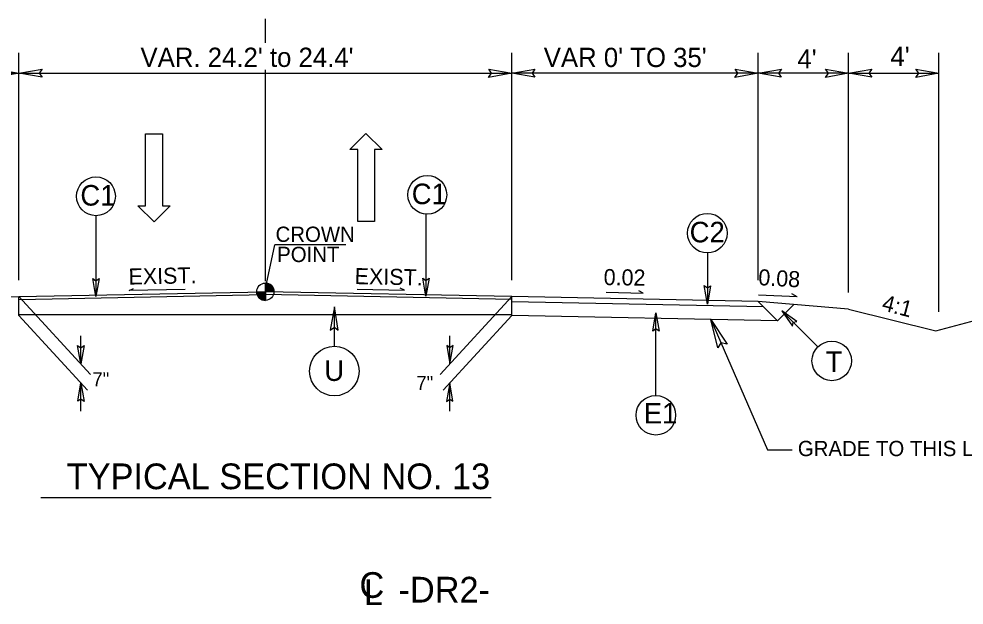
# Model space of a CAD drawing. Extents: x 573813 to 575363, y -54752 to -53123.
# Drawn here: x 574833.5 to 574917.3, y -54169.1 to -54117.2 of the extents above; entities that cross this region are included whole.
import ezdxf

# ---------------------------------------------------------------- set-up
doc = ezdxf.new("R2010")
doc.units = 0
for name, color, linetype in [('Exist CMT Alignment Centerline', 7, 'Continuous'), ('Exist CMT Ground Line', 7, 'Continuous'), ('Old_Level_1', 7, 'Continuous'), ('Old_Level_11', 7, 'Continuous'), ('Old_Level_2', 7, 'Continuous'), ('Old_Level_3', 7, 'Continuous'), ('Pattern 4', 7, 'Continuous'), ('Prop Dimension', 7, 'Continuous'), ('Prop Dimension Text', 7, 'Continuous'), ('Prop Lane Arrow CELL', 7, 'Continuous'), ('Prop Pavement Schedule Description CELL', 7, 'Continuous'), ('Typical Grade Point Symbol CELL', 7, 'Continuous'), ('Typical ID Circle CELL', 7, 'Continuous'), ('Typical Pavement Slope CELL', 7, 'Continuous'), ('Typical Pavement Slope Information CELL', 7, 'Continuous'), ('Typical Shoulder Slope Information CELL', 7, 'Continuous'), ('Typical Terminator CELL', 7, 'Continuous'), ('Typical Text General CELL', 7, 'Continuous'), ('Typical Text ID Circle CELL', 7, 'Continuous'), ('Typical Text Label CELL', 7, 'Continuous')]:
    doc.layers.add(name, color=color, linetype=linetype)

msp = doc.modelspace()

# ---------------------------------------------------------------- linework, layer by layer
at = {"layer": 'Exist CMT Alignment Centerline'}
for p, q in [((574833.535, -54143.346), (574833.535, -54141.771)), ((574833.535, -54143.346), (574833.535, -54141.771)), ((574833.535, -54143.439), (574833.535, -54142.246)), ((574877.195, -54143.346), (574877.195, -54141.771)), ((574877.195, -54143.439), (574877.195, -54142.246))]:
    msp.add_line(p, q, dxfattribs=at)
at = {"layer": 'Exist CMT Ground Line'}
for p, q in [((574833.54, -54142.021), (574855.37, -54141.584)), ((574877.19, -54142.021), (574855.36, -54141.584)), ((574833.535, -54143.346), (574877.195, -54143.346))]:
    msp.add_line(p, q, dxfattribs=at)
at = {"layer": 'Old_Level_1'}
for p, q in [((574914.76, -54144.8), (574933.236, -54139.865)), ((574833.535, -54141.771), (574855.365, -54141.334)), ((574843.311, -54141.23), (574843.691, -54141.041)), ((574848.249, -54141.128), (574843.311, -54141.23)), ((574863.489, -54141.116), (574867.686, -54141.204)), ((574867.686, -54141.204), (574867.307, -54141.014)), ((574885.567, -54141.387), (574888.836, -54141.455)), ((574888.836, -54141.455), (574888.457, -54141.265)), ((574902.47, -54141.8), (574902.016, -54141.508)), ((574811.705, -54142.207), (574833.535, -54141.771)), ((574899.024, -54142.207), (574877.195, -54141.771)), ((574899.489, -54142.671), (574877.204, -54142.226)), ((574907.039, -54142.87), (574899.024, -54142.207)), ((574899.024, -54142.207), (574900.727, -54143.91)), ((574902.47, -54141.8), (574899.041, -54141.634)), ((574902.169, -54142.467), (574900.727, -54143.91)), ((574907.039, -54142.87), (574914.76, -54144.8)), ((574900.727, -54143.91), (574877.204, -54143.439))]:
    msp.add_line(p, q, dxfattribs=at)
at = {"layer": 'Old_Level_11'}
for p, q in [((574915.043, -54143.1), (574915.043, -54120.185)), ((574907.039, -54122.004), (574915.043, -54122.004)), ((574855.365, -54141.05), (574856.217, -54137.177)), ((574862.482, -54137.177), (574856.217, -54137.177))]:
    msp.add_line(p, q, dxfattribs=at)
for points in [[(574831.488, -54121.651), (574833.535, -54122.004), (574831.477, -54122.367), (574831.738, -54122.004)], [(574835.581, -54122.356), (574833.535, -54122.004), (574835.593, -54121.64), (574835.331, -54122.004)], [(574875.148, -54121.651), (574877.195, -54122.004), (574875.137, -54122.367), (574875.398, -54122.004)], [(574879.241, -54122.356), (574877.195, -54122.004), (574879.252, -54121.64), (574878.991, -54122.004)], [(574896.978, -54121.651), (574899.024, -54122.004), (574896.967, -54122.367), (574897.228, -54122.004)], [(574901.071, -54122.356), (574899.024, -54122.004), (574901.082, -54121.64), (574900.821, -54122.004)], [(574904.993, -54121.651), (574907.039, -54122.004), (574904.982, -54122.367), (574905.243, -54122.004)], [(574909.086, -54122.356), (574907.039, -54122.004), (574909.097, -54121.64), (574908.836, -54122.004)], [(574912.997, -54121.652), (574915.043, -54122.004), (574912.986, -54122.368), (574913.247, -54122.004)]]:
    msp.add_lwpolyline(points, close=True, dxfattribs=at)
at = {"layer": 'Pattern 4'}
for p, q in [((574855.365, -54119.319), (574855.365, -54117.194)), ((574855.365, -54140.404), (574855.365, -54121.703))]:
    msp.add_line(p, q, dxfattribs=at)
at = {"layer": 'Prop Dimension'}
for p, q in [((574833.535, -54140.315), (574833.535, -54120.185)), ((574833.535, -54140.315), (574833.535, -54120.185)), ((574877.195, -54140.315), (574877.195, -54120.185)), ((574899.024, -54140.315), (574899.024, -54120.185)), ((574907.039, -54141.391), (574907.039, -54120.185)), ((574811.705, -54122.004), (574833.535, -54122.004)), ((574833.535, -54122.004), (574855.364, -54122.004)), ((574855.364, -54122.004), (574877.195, -54122.004)), ((574899.024, -54122.004), (574877.195, -54122.004)), ((574907.039, -54122.004), (574899.024, -54122.004)), ((574833.535, -54141.771), (574839.873, -54148.652)), ((574877.195, -54141.771), (574870.856, -54148.652)), ((574833.526, -54143.439), (574839.616, -54150.051)), ((574877.204, -54143.439), (574871.114, -54150.051)), ((574894.837, -54143.79), (574899.84, -54155.337)), ((574899.84, -54155.337), (574902.045, -54155.337))]:
    msp.add_line(p, q, dxfattribs=at)
at = {"layer": 'Prop Lane Arrow CELL'}
for p, q in [((574844.752, -54133.72), (574844.752, -54127.353)), ((574844.752, -54127.353), (574846.253, -54127.353)), ((574846.253, -54127.353), (574846.253, -54133.72)), ((574862.861, -54128.751), (574864.271, -54127.319)), ((574864.271, -54127.319), (574865.726, -54128.751)), ((574863.543, -54128.751), (574862.861, -54128.751)), ((574863.543, -54135.118), (574863.543, -54128.751)), ((574865.726, -54128.751), (574865.044, -54128.751)), ((574865.044, -54128.751), (574865.044, -54135.118)), ((574845.525, -54135.152), (574844.07, -54133.72)), ((574844.07, -54133.72), (574844.752, -54133.72)), ((574846.935, -54133.72), (574845.525, -54135.152)), ((574846.253, -54133.72), (574846.935, -54133.72)), ((574865.044, -54135.118), (574863.543, -54135.118))]:
    msp.add_line(p, q, dxfattribs=at)
at = {"layer": 'Typical Grade Point Symbol CELL'}
for p, q in [((574855.365, -54141.334), (574855.365, -54140.571)), ((574854.601, -54141.334), (574855.365, -54141.334)), ((574855.363, -54142.097), (574855.365, -54141.334)), ((574855.365, -54141.334), (574855.363, -54142.097)), ((574856.128, -54141.334), (574855.365, -54141.334))]:
    msp.add_line(p, q, dxfattribs=at)
for points in [[(574855.372, -54140.571), (574855.372, -54140.571), (574855.372, -54141.334)], [(574855.387, -54140.571), (574855.387, -54141.334)], [(574855.402, -54140.572), (574855.402, -54141.334)], [(574855.417, -54140.572), (574855.417, -54141.334)], [(574855.433, -54140.574), (574855.433, -54141.334)], [(574855.448, -54140.576), (574855.448, -54141.334)], [(574855.463, -54140.577), (574855.463, -54141.334)], [(574855.478, -54140.579), (574855.478, -54141.334)], [(574855.494, -54140.581), (574855.494, -54141.334)], [(574855.509, -54140.584), (574855.509, -54141.334)], [(574855.524, -54140.588), (574855.524, -54141.334)], [(574855.539, -54140.591), (574855.539, -54141.334)], [(574855.555, -54140.594), (574855.555, -54141.334)], [(574855.57, -54140.599), (574855.57, -54141.334)], [(574855.585, -54140.603), (574855.585, -54141.334)], [(574855.6, -54140.608), (574855.6, -54141.334)], [(574855.616, -54140.613), (574855.616, -54141.334)], [(574855.631, -54140.618), (574855.631, -54141.334)], [(574855.646, -54140.625), (574855.646, -54141.334)], [(574855.662, -54140.632), (574855.662, -54141.334)], [(574855.677, -54140.639), (574855.677, -54141.334)], [(574855.692, -54140.645), (574855.692, -54141.334)], [(574855.707, -54140.652), (574855.707, -54141.334)], [(574855.723, -54140.661), (574855.723, -54141.334)], [(574855.738, -54140.669), (574855.738, -54141.334)], [(574855.753, -54140.678), (574855.753, -54141.334)], [(574855.768, -54140.686), (574855.768, -54141.334)], [(574855.784, -54140.696), (574855.784, -54141.334)], [(574854.605, -54141.334), (574854.605, -54141.417)], [(574854.62, -54141.334), (574854.62, -54141.507)], [(574854.635, -54141.334), (574854.635, -54141.561)], [(574854.651, -54141.334), (574854.651, -54141.607)], [(574854.666, -54141.334), (574854.666, -54141.643)], [(574854.681, -54141.334), (574854.681, -54141.675)], [(574854.696, -54141.334), (574854.696, -54141.704)], [(574854.712, -54141.334), (574854.712, -54141.731)], [(574854.727, -54141.334), (574854.727, -54141.755)], [(574854.742, -54141.334), (574854.742, -54141.777)], [(574854.757, -54141.334), (574854.757, -54141.797)], [(574854.773, -54141.334), (574854.773, -54141.816)], [(574854.788, -54141.334), (574854.788, -54141.834)], [(574854.803, -54141.334), (574854.803, -54141.851)], [(574854.819, -54141.334), (574854.819, -54141.868)], [(574854.834, -54141.334), (574854.834, -54141.884)], [(574854.849, -54141.334), (574854.849, -54141.897)], [(574854.864, -54141.334), (574854.864, -54141.911)], [(574854.88, -54141.334), (574854.88, -54141.924)], [(574854.895, -54141.334), (574854.895, -54141.936)], [(574854.91, -54141.334), (574854.91, -54141.948)], [(574854.925, -54141.334), (574854.925, -54141.958)], [(574854.941, -54141.334), (574854.941, -54141.968)], [(574854.956, -54141.334), (574854.956, -54141.979)], [(574854.971, -54141.334), (574854.971, -54141.989)], [(574854.986, -54141.334), (574854.986, -54141.997)], [(574855.002, -54141.334), (574855.002, -54142.006)], [(574855.017, -54141.334), (574855.017, -54142.014)], [(574855.032, -54141.334), (574855.032, -54142.021)], [(574855.048, -54141.334), (574855.048, -54142.028)], [(574855.063, -54141.334), (574855.063, -54142.035)], [(574855.078, -54141.334), (574855.078, -54142.041)], [(574855.093, -54141.334), (574855.093, -54142.048)], [(574855.109, -54141.334), (574855.109, -54142.053)], [(574855.124, -54141.334), (574855.124, -54142.058)], [(574855.139, -54141.334), (574855.139, -54142.063)], [(574855.154, -54141.334), (574855.154, -54142.067)], [(574855.17, -54141.334), (574855.17, -54142.072)], [(574855.185, -54141.334), (574855.185, -54142.075)], [(574855.2, -54141.334), (574855.2, -54142.079)], [(574855.215, -54141.334), (574855.215, -54142.082)], [(574855.231, -54141.334), (574855.231, -54142.085)], [(574855.246, -54141.334), (574855.246, -54142.087)], [(574855.261, -54141.334), (574855.261, -54142.091)], [(574855.277, -54141.334), (574855.277, -54142.092)], [(574855.292, -54141.334), (574855.292, -54142.094)], [(574855.307, -54141.334), (574855.307, -54142.096)], [(574855.322, -54141.334), (574855.322, -54142.096)], [(574855.338, -54141.334), (574855.338, -54142.097)], [(574855.353, -54141.334), (574855.353, -54142.097), (574855.353, -54142.097)], [(574855.799, -54140.706), (574855.799, -54141.334)], [(574855.814, -54140.718), (574855.814, -54141.334)], [(574855.83, -54140.728), (574855.83, -54141.334)], [(574855.845, -54140.74), (574855.845, -54141.334)], [(574855.86, -54140.754), (574855.86, -54141.334)], [(574855.875, -54140.767), (574855.875, -54141.334)], [(574855.891, -54140.781), (574855.891, -54141.334)], [(574855.906, -54140.796), (574855.906, -54141.334)], [(574855.921, -54140.812), (574855.921, -54141.334)], [(574855.936, -54140.829), (574855.936, -54141.334)], [(574855.952, -54140.847), (574855.952, -54141.334)], [(574855.967, -54140.866), (574855.967, -54141.334)], [(574855.982, -54140.886), (574855.982, -54141.334)], [(574855.997, -54140.908), (574855.997, -54141.334)], [(574856.013, -54140.932), (574856.013, -54141.334)], [(574856.028, -54140.957), (574856.028, -54141.334)], [(574856.043, -54140.985), (574856.043, -54141.334)], [(574856.058, -54141.017), (574856.058, -54141.334)], [(574856.074, -54141.052), (574856.074, -54141.334)], [(574856.089, -54141.095), (574856.089, -54141.334)], [(574856.104, -54141.147), (574856.104, -54141.334)], [(574856.12, -54141.225), (574856.12, -54141.334)]]:
    msp.add_lwpolyline(points, dxfattribs=at)
msp.add_circle((574855.364, -54141.334), 0.763, dxfattribs=at)
for start, end in [(359.99048, 89.99048), (179.99048, 269.99048)]:
    msp.add_arc((574855.364, -54141.334), 0.763, start, end, dxfattribs=at)
at = {"layer": 'Typical ID Circle CELL'}
for p, q in [((574840.357, -54134.606), (574840.357, -54141.755)), ((574869.59, -54134.476), (574869.59, -54141.73)), ((574894.52, -54137.905), (574894.52, -54142.426)), ((574861.475, -54146.159), (574861.475, -54142.678)), ((574889.959, -54150.52), (574889.959, -54143.199)), ((574904.305, -54146.219), (574901.106, -54143.022)), ((574839.022, -54147.728), (574839.022, -54145.232)), ((574871.707, -54147.728), (574871.707, -54145.232)), ((574839.022, -54151.905), (574839.022, -54149.409)), ((574871.707, -54151.905), (574871.707, -54149.409))]:
    msp.add_line(p, q, dxfattribs=at)
for centre, radius in [((574840.357, -54132.888), 1.718), ((574869.712, -54132.763), 1.718), ((574894.52, -54136.156), 1.75), ((574905.54, -54147.456), 1.75), ((574861.475, -54148.357), 2.198), ((574889.959, -54152.269), 1.75)]:
    msp.add_circle(centre, radius, dxfattribs=at)
at = {"layer": 'Typical Pavement Slope CELL'}
for p, q in [((574877.195, -54141.771), (574855.365, -54141.334)), ((574833.535, -54143.439), (574833.535, -54141.771)), ((574877.195, -54143.439), (574877.195, -54141.771)), ((574877.204, -54143.439), (574877.204, -54142.226))]:
    msp.add_line(p, q, dxfattribs=at)
at = {"layer": 'Typical Terminator CELL'}
for points in [[(574840.631, -54140.165), (574840.357, -54141.755), (574840.074, -54140.156), (574840.357, -54140.359)], [(574869.864, -54140.14), (574869.59, -54141.73), (574869.308, -54140.131), (574869.59, -54140.334)], [(574894.799, -54140.806), (574894.52, -54142.426), (574894.232, -54140.797), (574894.52, -54141.004)], [(574861.828, -54144.724), (574861.475, -54142.678), (574861.111, -54144.736), (574861.475, -54144.474)], [(574889.68, -54144.819), (574889.959, -54143.199), (574890.247, -54144.828), (574889.959, -54144.621)], [(574902.449, -54143.97), (574901.106, -54143.022), (574902.055, -54144.377), (574902.112, -54144.027)], [(574895.45, -54146.312), (574894.837, -54143.79), (574896.277, -54145.969), (574895.73, -54145.85)], [(574839.301, -54146.108), (574839.022, -54147.728), (574838.734, -54146.099), (574839.022, -54146.306)], [(574871.428, -54146.108), (574871.707, -54147.728), (574871.995, -54146.099), (574871.707, -54146.306)], [(574838.743, -54151.029), (574839.022, -54149.409), (574839.31, -54151.038), (574839.022, -54150.831)], [(574871.986, -54151.029), (574871.707, -54149.409), (574871.419, -54151.038), (574871.707, -54150.831)]]:
    msp.add_lwpolyline(points, close=True, dxfattribs=at)
at = {"layer": 'Typical Text Label CELL'}
msp.add_line((574835.473, -54159.536), (574875.366, -54159.536), dxfattribs=at)

# ---------------------------------------------------------------- texts
at = {"layer": 'Old_Level_1'}
for s, rotation, p in [('EXIST.', 1.19188, (574843.256, -54140.706)), ('EXIST.', 358.80838, (574863.266, -54140.658)), ('4:1', 345.34321, (574909.903, -54142.949))]:
    msp.add_text(s, height=1.4212, rotation=rotation, dxfattribs=at).set_placement(p)
at = {"layer": 'Old_Level_11'}
msp.add_text("4'", height=1.7055, rotation=359.99996, dxfattribs=at).set_placement((574910.743, -54121.354))
at = {"layer": 'Old_Level_2'}
for s, rotation, p in [('C', 359.99996, (574863.7, -54168.427)), ('L', 359.94686, (574864.087, -54169.063))]:
    msp.add_text(s, height=2.274, rotation=rotation, dxfattribs=at).set_placement(p)
at = {"layer": 'Old_Level_3'}
for s, height, rotation, p in [('CROWN', 1.3502, 359.99996, (574856.269, -54136.925)), ('POINT', 1.3502, 359.99996, (574856.409, -54138.708)), ('-DR2-', 2.2739, 0, (574867.159, -54168.839))]:
    msp.add_text(s, height=height, rotation=rotation, dxfattribs=at).set_placement(p)
at = {"layer": 'Prop Dimension'}
msp.add_text("VAR. 24.2' to 24.4'", height=1.70546, dxfattribs=at).set_placement((574844.303, -54121.442))
at = {"layer": 'Prop Dimension Text'}
for s, height, p in [("VAR 0' TO 35'", 1.70546, (574880.028, -54121.452)), ("4'", 1.7055, (574902.5, -54121.579))]:
    msp.add_text(s, height=height, dxfattribs=at).set_placement(p)
at = {"layer": 'Prop Pavement Schedule Description CELL'}
for p in [(574838.977, -54133.713), (574868.332, -54133.588)]:
    msp.add_text('C1', height=1.8192, rotation=360, dxfattribs=at).set_placement(p)
at = {"layer": 'Typical Pavement Slope Information CELL'}
msp.add_text('0.02', height=1.4212, rotation=359.08986, dxfattribs=at).set_placement((574885.328, -54140.742))
at = {"layer": 'Typical Shoulder Slope Information CELL'}
msp.add_text('0.08', height=1.4212, rotation=356.75309, dxfattribs=at).set_placement((574899.008, -54140.747))
at = {"layer": 'Typical Text General CELL'}
msp.add_text('GRADE TO THIS LINE', height=1.34982, dxfattribs=at).set_placement((574902.538, -54155.882))
at = {"layer": 'Typical Text ID Circle CELL'}
for s, height, p in [('C2', 1.8192, (574892.954, -54136.966)), ('T', 1.819, (574905.004, -54148.432)), ('U', 1.819, (574860.587, -54149.228)), ('7"', 1.2298, (574840.038, -54149.696)), ('7"', 1.2298, (574868.738, -54150.021)), ('E1', 1.8192, (574888.884, -54152.992))]:
    msp.add_text(s, height=height, dxfattribs=at).set_placement(p)
at = {"layer": 'Typical Text Label CELL'}
msp.add_text('TYPICAL SECTION NO. 13', height=2.27395, dxfattribs=at).set_placement((574837.765, -54158.809))

doc.saveas('drawing.dxf')
